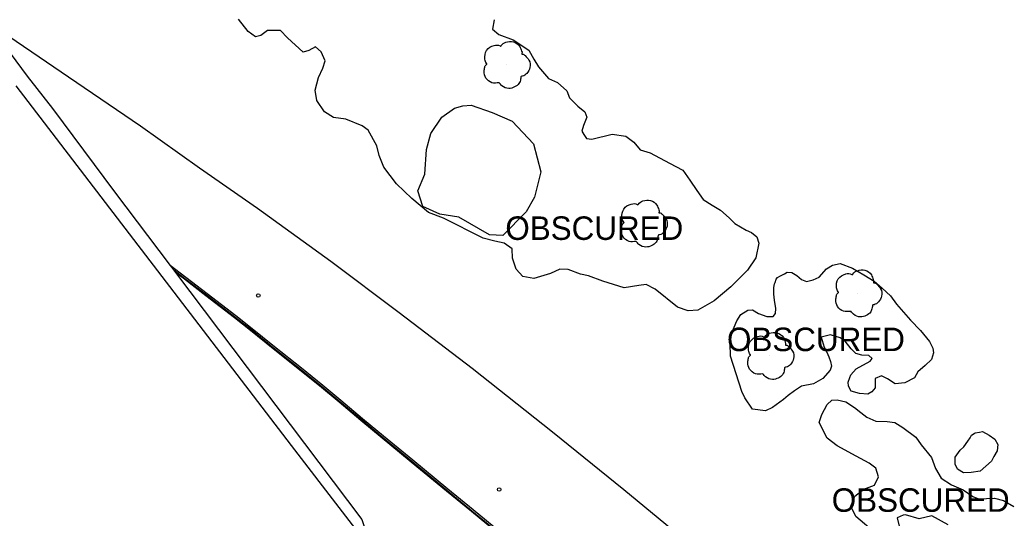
# Model space of a CAD drawing. Extents: x 368532 to 392481, y 10654822 to 10676899.
# Drawn here: x 369895.1 to 370105.8, y 10675415.4 to 10675521.5 of the extents above; entities that cross this region are included whole.
import ezdxf

# ---------------------------------------------------------------- set-up
doc = ezdxf.new("R2010")
doc.units = 0
for name, color, linetype in [('p_bridge deck', 7, 'Continuous'), ('p_dtm obscured area', 7, 'Continuous'), ('p_railroad rr control', 7, 'Continuous'), ('p_road - paved curb', 7, 'Continuous'), ('p_structure unidentified', 7, 'Continuous'), ('p_veg tree', 7, 'Continuous'), ('p_veg woods', 7, 'Continuous')]:
    doc.layers.add(name, color=color, linetype=linetype)

msp = doc.modelspace()

# ---------------------------------------------------------------- linework, layer by layer
at = {"layer": 'p_bridge deck'}
msp.add_lwpolyline([(369894.22, 10675507.44), (369927.91, 10675463.47), (369952.9, 10675430.84), (369974.61, 10675402.63)], dxfattribs=at)
at = {"layer": 'p_dtm obscured area'}
for points in [[(369876.87, 10675536.23), (369896.64, 10675509.47), (369902.06, 10675502.58), (369915.24, 10675484.87), (369927.1, 10675469.2), (369927.88, 10675468.16), (369928.22, 10675467.71), (369967.92, 10675415.13), (369967.95, 10675415.11), (369968.01, 10675414.87), (369968.21, 10675414.26), (369969.68, 10675409.88), (369969.71, 10675409.79), (369970.03, 10675408.86), (369970.03, 10675408.84), (369970.24, 10675408.23), (369971.39, 10675406.84), (369980.25, 10675396.06)], [(369996.1, 10675521.49), (369995.76, 10675519.51), (369997.12, 10675518.37), (370000.19, 10675517.25), (370003.51, 10675515.03), (370004.56, 10675513.14), (370005.57, 10675511.5), (370007.7, 10675509), (370009.61, 10675508.17), (370011.6, 10675506.34), (370012.18, 10675504.89), (370013.93, 10675503.11), (370015.41, 10675501.92), (370015.83, 10675500.77), (370015.11, 10675498.97), (370014.79, 10675497.79), (370015.22, 10675497.07), (370015.8, 10675496.21), (370016.94, 10675496.09), (370021.23, 10675497.12), (370024.18, 10675496.71), (370025.86, 10675495.44), (370027.19, 10675493.79), (370029.32, 10675493.14), (370033.46, 10675490.98), (370036.32, 10675489.45), (370037.75, 10675487.38), (370039.27, 10675485.16), (370040.63, 10675483.25), (370042.57, 10675482.03), (370044.35, 10675480.99), (370046.18, 10675479.36), (370047.35, 10675478.13), (370049.8, 10675476.69), (370050.91, 10675476.23), (370052.09, 10675475.31), (370052.46, 10675473.93), (370051.82, 10675470.8), (370050.05, 10675468.21), (370046.53, 10675464.61), (370042.98, 10675461.64), (370039.48, 10675459.67), (370037.4, 10675459.55), (370035.15, 10675460.31), (370030.42, 10675464.15), (370028.47, 10675465.12), (370026.94, 10675464.94), (370023.8, 10675464.44), (370019.27, 10675465.81), (370016.17, 10675466.96), (370014.53, 10675467.32), (370011.86, 10675468.34), (370010.1, 10675468.38), (370008.08, 10675467.49), (370004.59, 10675466.43), (370002.21, 10675466.87), (370000.83, 10675468.41), (370000.05, 10675470.71), (369999.91, 10675472.76), (369998.26, 10675473.94), (369996.28, 10675474.34), (369993.74, 10675475.03), (369985.35, 10675479.29), (369982.16, 10675480.46), (369978.59, 10675483.47), (369975.32, 10675486.58), (369972.63, 10675490.14), (369971.64, 10675492.58), (369971.15, 10675494.66), (369969.3, 10675498), (369967.98, 10675498.94), (369964.53, 10675500.31), (369961.86, 10675500.68), (369959.99, 10675501.91), (369958.34, 10675504.34), (369957.97, 10675506.49), (369958.73, 10675509.18), (369959.62, 10675511.21), (369960.09, 10675512.74), (369959.27, 10675514.7), (369958.05, 10675515.76), (369956.66, 10675514.96), (369955.42, 10675514.62), (369952.1, 10675517.67), (369950.61, 10675519.2), (369947.82, 10675519.2), (369946.44, 10675518.17), (369945.31, 10675517.89), (369943.72, 10675519.02), (369941.64, 10675521.64)], [(370077.3, 10675412.22), (370073.16, 10675415.74), (370072.04, 10675417.92), (370072.92, 10675420.07), (370074.82, 10675421.54), (370077.09, 10675422.41), (370077.99, 10675424.16), (370077.4, 10675426.01), (370076.01, 10675427.07), (370073.18, 10675428.57), (370069.18, 10675430.82), (370067.03, 10675432.41), (370065.32, 10675435.78), (370065.88, 10675437.46), (370067.04, 10675439.62), (370068, 10675440.54), (370069.19, 10675440.59), (370071.03, 10675440.16), (370072.85, 10675438.93), (370074.21, 10675437.9), (370075.51, 10675436.88), (370077.37, 10675436.04), (370079.79, 10675435.95), (370081.48, 10675435.76), (370083.18, 10675434.7), (370085.95, 10675432.65), (370087.07, 10675431.02), (370089.27, 10675428.29), (370090.08, 10675425.96), (370091.33, 10675423.93), (370093.54, 10675422.46), (370096, 10675421.45), (370098.09, 10675419.98), (370099.3, 10675419.52), (370102.66, 10675419.66), (370104.62, 10675419.12), (370106.78, 10675417.9)], [(370092.79, 10675413.96), (370089.31, 10675415.9), (370086.66, 10675415.21), (370083.69, 10675416.08), (370083.24, 10675416.06), (370081.92, 10675415.47), (370082.4, 10675413.66)]]:
    msp.add_lwpolyline(points, dxfattribs=at)
for points in [[(370061.6, 10675443.46), (370060.11, 10675442.48), (370058.75, 10675441.49), (370057.73, 10675440.67), (370055.41, 10675438.98), (370053.93, 10675438.26), (370051.1, 10675438.56), (370049.48, 10675441.03), (370048.85, 10675442.37), (370046.48, 10675449.85), (370046.34, 10675452.55), (370046.55, 10675454.27), (370047.24, 10675456.04), (370047.78, 10675457.4), (370048.66, 10675458.78), (370050.11, 10675459.69), (370051.1, 10675459.77), (370052.42, 10675458.94), (370054.18, 10675458.3), (370055.52, 10675458.33), (370056.01, 10675458.98), (370056.07, 10675460.06), (370055.83, 10675461.82), (370055.66, 10675463.07), (370055.68, 10675464.52), (370055.79, 10675465.3), (370055.95, 10675465.53), (370056.15, 10675466.28), (370056.45, 10675466.61), (370056.92, 10675466.94), (370057.92, 10675467.44), (370058.48, 10675467.75), (370059.51, 10675467.68), (370060.59, 10675467.07), (370061.54, 10675466.2), (370062.61, 10675465.76), (370064.02, 10675466.16), (370065.36, 10675466.73), (370066.88, 10675468.45), (370068.19, 10675469.28), (370069.8, 10675469.6), (370072.44, 10675468.6), (370074.83, 10675467.17), (370077.03, 10675465.86), (370078.74, 10675464.34), (370080.52, 10675462.71), (370081.82, 10675460.97), (370084.79, 10675457.53), (370086.91, 10675455.32), (370088.8, 10675453.03), (370089.55, 10675451.58), (370089.71, 10675450.56), (370089.23, 10675449.15), (370087.94, 10675447.92), (370086.38, 10675446.52), (370085.66, 10675445.26), (370083.57, 10675444.23), (370081.55, 10675444), (370079.89, 10675445.04), (370078.58, 10675445.7), (370077.29, 10675445.13), (370077.29, 10675443.11), (370076.56, 10675442.31), (370075.69, 10675441.78), (370073.92, 10675441.94), (370072.13, 10675442.43), (370071.6, 10675443.46), (370071.54, 10675444.34), (370071.86, 10675445.35), (370072.04, 10675445.9), (370073.24, 10675447.21), (370076.16, 10675448.79), (370076.62, 10675449.35), (370075.94, 10675450.03), (370074.4, 10675450.08), (370073.16, 10675450.45), (370072.18, 10675451.41), (370070.88, 10675453.09), (370069.77, 10675453.78), (370067.72, 10675454.41), (370065.77, 10675453.9), (370066.4, 10675451.79), (370066.99, 10675450.76), (370067.37, 10675449.75), (370067.76, 10675448.74), (370067.97, 10675447.78), (370067.67, 10675446.91), (370066.09, 10675445.13), (370064.09, 10675444.02)], [(370102.07, 10675427.53), (370099.59, 10675425.37), (370097.7, 10675425.09), (370096.1, 10675425.02), (370094.79, 10675425.79), (370094.29, 10675426.85), (370094.28, 10675428.39), (370095.33, 10675429.83), (370096.15, 10675430.55), (370097.01, 10675431.78), (370097.46, 10675432.52), (370097.78, 10675433.04), (370098.37, 10675433.38), (370098.56, 10675433.53), (370099.49, 10675433.72), (370100.09, 10675433.83), (370101.54, 10675433.09), (370102.78, 10675432.17), (370103.4, 10675431.06), (370103.23, 10675429.69), (370102.51, 10675428.49)]]:
    msp.add_lwpolyline(points, close=True, dxfattribs=at)
at = {"layer": 'p_railroad rr control'}
msp.add_lwpolyline([(369887.97, 10675521.2), (369905.44, 10675509.37), (369920.8, 10675498.91), (369933.34, 10675489.96), (369945.73, 10675481.4), (369961.34, 10675470.1), (369975.85, 10675459.16), (369991.41, 10675447.3), (370008.54, 10675433.78), (370023.73, 10675421.52), (370039.97, 10675408.06), (370054.52, 10675395.59), (370069.02, 10675382.57), (370085, 10675367.81), (370099.33, 10675354.8), (370116.48, 10675338.26), (370132.79, 10675322.13), (370146.81, 10675307.31), (370161.37, 10675291.66), (370183.24, 10675267.66)], dxfattribs=at)
at = {"layer": 'p_road - paved curb'}
for p, q in [((369930.44, 10675466.65), (369927.1, 10675469.2)), ((369930.23, 10675466.37), (369927.88, 10675468.16)), ((369930.14, 10675466.25), (369928.22, 10675467.71)), ((369934.72, 10675462.73), (369930.14, 10675466.25)), ((369934.81, 10675462.85), (369930.23, 10675466.37)), ((369935.02, 10675463.13), (369930.44, 10675466.65)), ((369940.8, 10675458.06), (369934.72, 10675462.73)), ((369940.89, 10675458.18), (369934.81, 10675462.85)), ((369941.11, 10675458.45), (369935.02, 10675463.13)), ((369944.24, 10675455.34), (369940.8, 10675458.06)), ((369944.33, 10675455.46), (369940.89, 10675458.18)), ((369944.55, 10675455.73), (369941.11, 10675458.45)), ((369949.02, 10675451.47), (369944.24, 10675455.34)), ((369949.11, 10675451.59), (369944.33, 10675455.46)), ((369949.33, 10675451.86), (369944.55, 10675455.73)), ((369954.75, 10675446.91), (369949.02, 10675451.47)), ((369954.84, 10675447.03), (369949.11, 10675451.59)), ((369955.06, 10675447.3), (369949.33, 10675451.86)), ((369959.32, 10675443.22), (369954.75, 10675446.91)), ((369959.42, 10675443.34), (369954.84, 10675447.03)), ((369959.64, 10675443.61), (369955.06, 10675447.3)), ((369963.13, 10675440.06), (369959.32, 10675443.22)), ((369963.23, 10675440.18), (369959.42, 10675443.34)), ((369963.45, 10675440.44), (369959.64, 10675443.61)), ((369967.74, 10675436.17), (369963.13, 10675440.06)), ((369967.84, 10675436.29), (369963.23, 10675440.18)), ((369968.06, 10675436.55), (369963.45, 10675440.44)), ((369972.24, 10675432.45), (369967.74, 10675436.17)), ((369972.34, 10675432.57), (369967.84, 10675436.29)), ((369972.56, 10675432.84), (369968.06, 10675436.55)), ((369978.46, 10675427.32), (369972.24, 10675432.45)), ((369978.56, 10675427.44), (369972.34, 10675432.57)), ((369978.78, 10675427.71), (369972.56, 10675432.84)), ((369985.93, 10675421.16), (369978.46, 10675427.32)), ((369986.03, 10675421.28), (369978.56, 10675427.44)), ((369986.25, 10675421.55), (369978.78, 10675427.71)), ((369991.29, 10675416.79), (369985.93, 10675421.16)), ((369991.38, 10675416.91), (369986.03, 10675421.28)), ((369991.61, 10675417.18), (369986.25, 10675421.55)), ((369998.24, 10675411.09), (369991.29, 10675416.79)), ((369998.34, 10675411.21), (369991.38, 10675416.91)), ((369998.56, 10675411.48), (369991.61, 10675417.18))]:
    msp.add_line(p, q, dxfattribs=at)
at = {"layer": 'p_structure unidentified'}
for centre in [(369945.87, 10675462.79), (369997.17, 10675421.49)]:
    msp.add_circle(centre, 0.375, dxfattribs=at)
at = {"layer": 'p_veg tree'}
for p, q in [((369998.67, 10675511.96), (369998.67, 10675511.96)), ((370027.88, 10675478.18), (370027.88, 10675478.18)), ((370073.57, 10675463.31), (370073.57, 10675463.31)), ((370054.83, 10675449.99), (370054.83, 10675449.99))]:
    msp.add_line(p, q, dxfattribs=at)
for points in [[(369997.18, 10675508.08), (369995.62, 10675508.1), (369994.35, 10675509.09), (369993.98, 10675510.55), (369994.11, 10675511.39), (369994.46, 10675512), (369994.56, 10675512.11), (369994.5, 10675512.2), (369994.14, 10675513.09), (369994.5, 10675514.98), (369996.1, 10675516.04), (369997.39, 10675515.94), (369997.53, 10675515.9), (369997.61, 10675515.99), (369998.59, 10675516.71), (370000.2, 10675516.82), (370001.55, 10675515.84), (370001.96, 10675514.83), (370002.02, 10675514.28), (370002, 10675514.17), (370002.1, 10675514.17), (370002.7, 10675513.86), (370003.53, 10675512.88), (370003.74, 10675511.33), (370003.09, 10675510.09), (370002.13, 10675509.48), (370001.87, 10675509.42), (370001.82, 10675509.38), (370001.81, 10675509.31), (370001.75, 10675508.86), (370001.4, 10675507.95), (370000.46, 10675507.19), (369999.23, 10675506.88), (369997.74, 10675507.45), (369997.16, 10675508.08)], [(370026.39, 10675474.3), (370024.83, 10675474.32), (370023.56, 10675475.31), (370023.19, 10675476.77), (370023.31, 10675477.61), (370023.67, 10675478.22), (370023.77, 10675478.33), (370023.71, 10675478.42), (370023.35, 10675479.31), (370023.71, 10675481.2), (370025.3, 10675482.26), (370026.6, 10675482.16), (370026.74, 10675482.11), (370026.82, 10675482.21), (370027.8, 10675482.93), (370029.41, 10675483.04), (370030.76, 10675482.06), (370031.17, 10675481.05), (370031.22, 10675480.5), (370031.21, 10675480.39), (370031.31, 10675480.39), (370031.91, 10675480.08), (370032.74, 10675479.1), (370032.94, 10675477.55), (370032.3, 10675476.31), (370031.34, 10675475.7), (370031.08, 10675475.64), (370031.03, 10675475.6), (370031.02, 10675475.53), (370030.96, 10675475.08), (370030.61, 10675474.17), (370029.67, 10675473.41), (370028.44, 10675473.1), (370026.95, 10675473.67), (370026.36, 10675474.3)], [(370072.07, 10675459.42), (370070.52, 10675459.45), (370069.24, 10675460.43), (370068.88, 10675461.89), (370069, 10675462.74), (370069.35, 10675463.35), (370069.46, 10675463.45), (370069.4, 10675463.55), (370069.03, 10675464.43), (370069.4, 10675466.33), (370070.99, 10675467.39), (370072.29, 10675467.29), (370072.43, 10675467.24), (370072.5, 10675467.34), (370073.48, 10675468.06), (370075.09, 10675468.17), (370076.45, 10675467.18), (370076.86, 10675466.17), (370076.91, 10675465.63), (370076.89, 10675465.51), (370077, 10675465.52), (370077.59, 10675465.21), (370078.42, 10675464.23), (370078.63, 10675462.67), (370077.98, 10675461.44), (370077.02, 10675460.83), (370076.77, 10675460.77), (370076.71, 10675460.72), (370076.71, 10675460.66), (370076.64, 10675460.21), (370076.3, 10675459.3), (370075.35, 10675458.54), (370074.13, 10675458.23), (370072.63, 10675458.8), (370072.05, 10675459.43)], [(370053.33, 10675446.11), (370051.77, 10675446.13), (370050.5, 10675447.12), (370050.14, 10675448.58), (370050.26, 10675449.42), (370050.61, 10675450.03), (370050.71, 10675450.14), (370050.65, 10675450.24), (370050.29, 10675451.12), (370050.65, 10675453.02), (370052.25, 10675454.07), (370053.55, 10675453.98), (370053.68, 10675453.93), (370053.76, 10675454.02), (370054.74, 10675454.75), (370056.35, 10675454.85), (370057.7, 10675453.87), (370058.11, 10675452.86), (370058.17, 10675452.31), (370058.15, 10675452.2), (370058.25, 10675452.2), (370058.85, 10675451.89), (370059.68, 10675450.92), (370059.89, 10675449.36), (370059.24, 10675448.13), (370058.28, 10675447.52), (370058.02, 10675447.46), (370057.97, 10675447.41), (370057.96, 10675447.35), (370057.9, 10675446.9), (370057.56, 10675445.98), (370056.61, 10675445.22), (370055.39, 10675444.92), (370053.89, 10675445.48), (370053.31, 10675446.12)]]:
    msp.add_spline(points, degree=3, dxfattribs=at)
at = {"layer": 'p_veg woods'}
msp.add_lwpolyline([(369985, 10675500.77), (369987.66, 10675502.69), (369989.45, 10675503.18), (369991.19, 10675503.28), (369995.67, 10675501.73), (369999.91, 10675499.91), (370004.48, 10675495.08), (370006.04, 10675489.12), (370004.71, 10675483.74), (370002.91, 10675480.61), (369997.99, 10675475.54), (369995.09, 10675475.69), (369988.6, 10675479.47), (369984.55, 10675480.1), (369980.93, 10675481.77), (369979.84, 10675485.06), (369981.35, 10675488.62), (369981.68, 10675493.91), (369982.59, 10675497.28)], close=True, dxfattribs=at)

# ---------------------------------------------------------------- texts
at = {"layer": 'p_dtm obscured area'}
for p in [(369996.63, 10675474.63), (370043.84, 10675450.95), (370066.15, 10675416.74)]:
    msp.add_text(' OBSCURED', height=5, dxfattribs=at).set_placement(p)

doc.saveas('drawing.dxf')
